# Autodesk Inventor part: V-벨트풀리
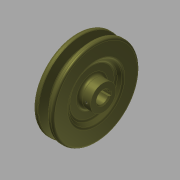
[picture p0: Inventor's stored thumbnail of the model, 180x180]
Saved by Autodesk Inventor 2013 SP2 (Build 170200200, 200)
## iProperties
Company: 한국ATC센터
Created: 2015-12
Part Number: V-벨트풀리
Document SubType Name: Modeling
Designer: mdu
Density: 7.25 g/cm^3
Mass: 594.58 g
Surface Area: 210.471 cm^2
Volume: 82.011 cm^3
Material: 주철
Author: mdu
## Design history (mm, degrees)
sketch "스케치1"
  geometry: L1 (-13, 0)-(13, 0); L2 (-13, 0)-(-13, 12.5); L3 (-13, 12.5)-(-9, 12.5); L4 (-9, 12.5)-(-9, 23); L5 (-9, 23)-(-13, 27); L6 (-13, 27)-(-13, 42.7); L7 (-13, 42.7)-(-8.325, 42.7); L8 (-8.325, 42.7)-(-5.574, 33.7); L9 (-5.574, 33.7)-(-1.426, 33.7); L10 (-1.426, 33.7)-(1.325, 42.7); L11 (1.325, 42.7)-(6, 42.7); L12 (6, 42.7)-(6, 27); L13 (6, 27)-(2, 23); L14 (2, 23)-(2, 12.5); L15 (2, 12.5)-(13, 12.5); L16 (13, 12.5)-(13, 0); L17 (-7.5, 40)-(0.5, 40); 2 further points
  constraints: 34 end point, 6 parallel, 5 collinear, 5 equal length, 4 perpendicular, 2 point on line, 1 coincident, 1 horizontal, 1 midpoint
  dimensions: "d0" = 26 distance of L1.start L1.end; "d1" = 2.7 distance between parallel lines of L7 L17; "d2" = 6.3 distance between parallel lines of L9 L17; "d3" = 8 distance of L17.start L17.end; "d4" = 34 deg angle of L10 L8; "d5" = 19 distance between parallel lines of L12 L6; "d7" = 25 diameter of L15 L1; "d8" = 46 diameter of L13.end L1; "d9" = 54 diameter of L12.end L1; "d10" = 4 distance between parallel lines of L2 L4; "d11" = 80 diameter of L17 L1
revolve "회전1" sketch "스케치1" stored, may be unused: angle "d12" = 90 deg
sketch "스케치2"
  geometry: L1 (-2, 5.657)-(-2, 7.8); L2 (-2, 7.8)-(2, 7.8); L3 (2, 7.8)-(2, 5.657); A1 r 6 centre (0, 0) between (-2, 5.657) and (2, 5.657); 1 further point
  constraints: 6 end point, 2 parallel, 2 point on circle, 1 centre point, 1 coincident, 1 perpendicular, 1 vertical
  dimensions: "d13" = 12 diameter of A1; "d14" = 13.8 dimension on A1 L2; "d15" = 4 distance of L1.end L2.end
extrude "돌출1" cut sketch "스케치2" stored distance "d16" = 10; taper "d17" = 0 deg
node "작업 평면1"
sketch "스케치3"
  geometry: L1 (-5.5, 12.5)-(-5.5, -12.5) reference; L2 (20.5, 27)-(20.5, -27) reference; 3 further points
  constraints: 1 horizontal alignment, 1 midpoint
  dimensions: "d18" = 4 distance from line of point (-1.5, 0) L1; "d33" = 22 distance from line of point (-1.5, 0) L2 (derived)
hole "구멍1" sketch "스케치3" at (-1.5, 0) diameter "d19" = 2.459; stored, may be unused: countersink angle "d23" = 90 deg, drill point angle "d25" = 118 deg; dims "d20" = 6, "d21" = 4, "d22" = 2, "d24" = 8
fillet "모깎기1" dims "d26" = 2, "d27" = 0.5, "d28" = 1, "d29" = 3
chamfer "모따기1" distance "d30" = 1; stored, may be unused: second distance "d31" = 2, angle "d32" = 45 deg
node "솔리드1"
